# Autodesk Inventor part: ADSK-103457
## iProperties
Shininess: 0.0
Created: 2000-03
Part Number: ADSK-103457
Document SubType Name: Modeling
Stock Number: ADSK-103457
Density: 1 g/cm^3
Density: 0.0
Volume: 0.0
Area: 0.0
PropertySet Name: Model Information
Control State: 0
Checked Out: False
Master: False
Author: gao
